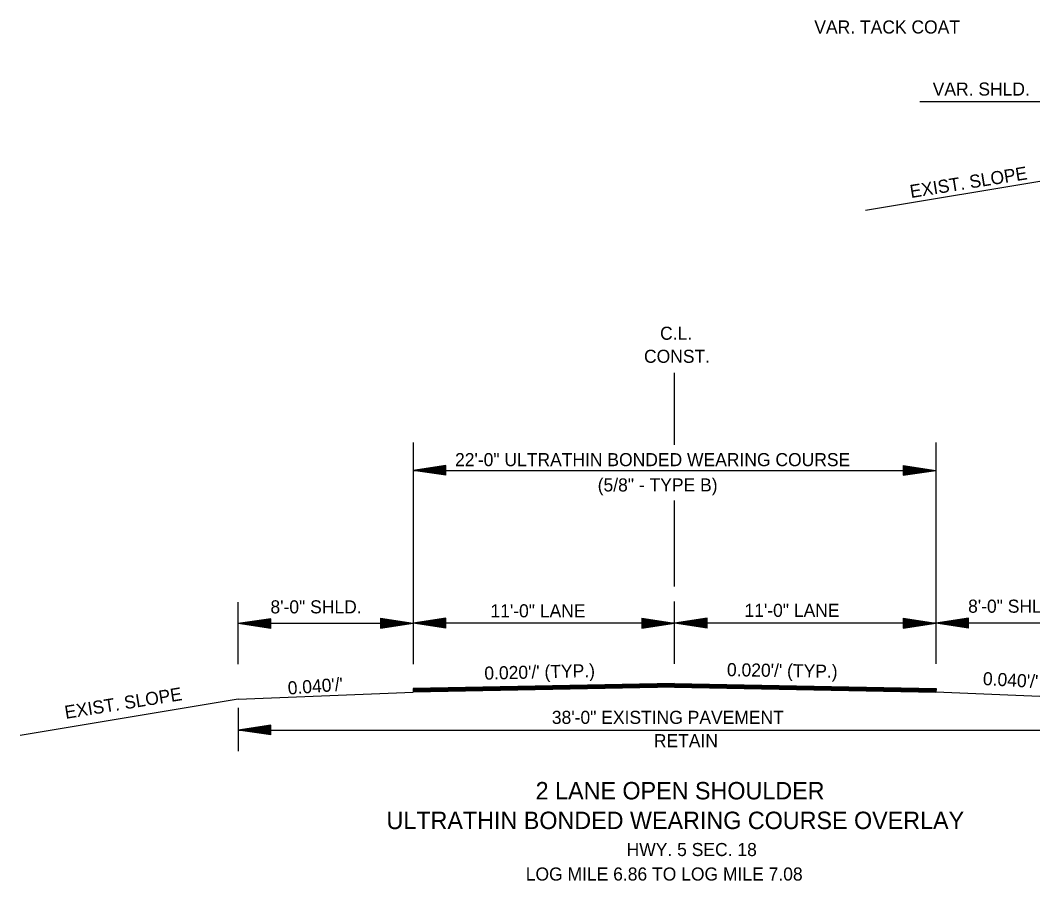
# Model space of a CAD drawing. Extents: x 2263886 to 2266026, y -3122850 to -3121850.
# Drawn here: x 2265375.37 to 2265421.84, y -3122647.18 to -3122607.69 of the extents above; entities that cross this region are included whole.
import ezdxf

# ---------------------------------------------------------------- set-up
doc = ezdxf.new("R2010")
doc.units = 0
doc.layers.add('Default', color=7, linetype='Continuous')
doc.layers.add('R_Border Prem', color=7, linetype='Continuous')

msp = doc.modelspace()

# ---------------------------------------------------------------- linework, layer by layer
at = {"layer": 'R_Border Prem'}
for p, q in [((2265428.196, -3122611.431), (2265416.655, -3122611.431)), ((2265424.167, -3122614.746), (2265414.16, -3122616.414)), ((2265405.399, -3122627.168), (2265405.399, -3122623.874)), ((2265393.399, -3122627.069), (2265393.399, -3122637.242)), ((2265394.899, -3122628.119), (2265393.399, -3122628.344)), ((2265394.899, -3122628.157), (2265393.65, -3122628.344)), ((2265394.899, -3122628.195), (2265393.908, -3122628.344)), ((2265394.899, -3122628.233), (2265394.158, -3122628.344)), ((2265394.899, -3122628.271), (2265394.412, -3122628.344)), ((2265394.899, -3122628.309), (2265394.662, -3122628.344)), ((2265394.899, -3122628.569), (2265394.899, -3122628.119)), ((2265415.892, -3122628.119), (2265417.392, -3122628.344)), ((2265415.892, -3122628.119), (2265415.892, -3122628.569)), ((2265415.892, -3122628.157), (2265417.142, -3122628.344)), ((2265415.892, -3122628.195), (2265416.884, -3122628.344)), ((2265415.892, -3122628.233), (2265416.634, -3122628.344)), ((2265415.892, -3122628.272), (2265416.38, -3122628.344)), ((2265415.892, -3122628.309), (2265416.129, -3122628.344)), ((2265393.399, -3122628.344), (2265417.392, -3122628.344)), ((2265394.899, -3122628.569), (2265393.399, -3122628.344)), ((2265394.899, -3122628.532), (2265393.65, -3122628.344)), ((2265394.899, -3122628.494), (2265393.908, -3122628.344)), ((2265394.899, -3122628.456), (2265394.158, -3122628.344)), ((2265394.899, -3122628.417), (2265394.412, -3122628.344)), ((2265394.899, -3122628.38), (2265394.662, -3122628.344)), ((2265415.892, -3122628.569), (2265417.392, -3122628.344)), ((2265415.892, -3122628.418), (2265416.38, -3122628.344)), ((2265415.892, -3122628.494), (2265416.884, -3122628.344)), ((2265415.892, -3122628.532), (2265417.142, -3122628.344)), ((2265415.892, -3122628.456), (2265416.634, -3122628.344)), ((2265415.892, -3122628.38), (2265416.129, -3122628.344)), ((2265405.399, -3122633.668), (2265405.399, -3122629.733)), ((2265385.373, -3122637.242), (2265385.373, -3122634.387)), ((2265405.399, -3122637.225), (2265405.399, -3122634.37)), ((2265386.873, -3122635.151), (2265385.373, -3122635.376)), ((2265386.873, -3122635.188), (2265385.624, -3122635.376)), ((2265386.873, -3122635.227), (2265385.882, -3122635.376)), ((2265386.873, -3122635.264), (2265386.132, -3122635.376)), ((2265386.873, -3122635.601), (2265386.873, -3122635.151)), ((2265391.899, -3122635.134), (2265393.399, -3122635.359)), ((2265391.899, -3122635.134), (2265391.899, -3122635.584)), ((2265391.899, -3122635.171), (2265393.149, -3122635.359)), ((2265391.899, -3122635.21), (2265392.891, -3122635.359)), ((2265391.899, -3122635.247), (2265392.641, -3122635.359)), ((2265391.899, -3122635.286), (2265392.387, -3122635.359)), ((2265394.899, -3122635.134), (2265393.399, -3122635.359)), ((2265394.899, -3122635.171), (2265393.65, -3122635.359)), ((2265394.899, -3122635.21), (2265393.908, -3122635.359)), ((2265394.899, -3122635.247), (2265394.158, -3122635.359)), ((2265394.899, -3122635.285), (2265394.412, -3122635.359)), ((2265394.899, -3122635.584), (2265394.899, -3122635.134)), ((2265403.899, -3122635.134), (2265405.399, -3122635.359)), ((2265403.899, -3122635.134), (2265403.899, -3122635.584)), ((2265403.899, -3122635.171), (2265405.149, -3122635.359)), ((2265403.899, -3122635.21), (2265404.891, -3122635.359)), ((2265403.899, -3122635.247), (2265404.641, -3122635.359)), ((2265403.899, -3122635.286), (2265404.387, -3122635.359)), ((2265406.899, -3122635.134), (2265405.399, -3122635.359)), ((2265406.899, -3122635.171), (2265405.65, -3122635.359)), ((2265406.899, -3122635.21), (2265405.908, -3122635.359)), ((2265406.899, -3122635.247), (2265406.158, -3122635.359)), ((2265406.899, -3122635.285), (2265406.412, -3122635.359)), ((2265406.899, -3122635.584), (2265406.899, -3122635.134)), ((2265415.892, -3122635.134), (2265417.392, -3122635.359)), ((2265415.892, -3122635.134), (2265415.892, -3122635.584)), ((2265415.892, -3122635.171), (2265417.142, -3122635.359)), ((2265415.892, -3122635.21), (2265416.884, -3122635.359)), ((2265415.892, -3122635.247), (2265416.634, -3122635.359)), ((2265415.892, -3122635.286), (2265416.38, -3122635.359)), ((2265418.892, -3122635.134), (2265417.392, -3122635.359)), ((2265418.892, -3122635.171), (2265417.643, -3122635.359)), ((2265418.892, -3122635.21), (2265417.901, -3122635.359)), ((2265418.892, -3122635.247), (2265418.15, -3122635.359)), ((2265418.892, -3122635.285), (2265418.405, -3122635.359)), ((2265418.892, -3122635.584), (2265418.892, -3122635.134)), ((2265393.399, -3122635.376), (2265385.373, -3122635.376)), ((2265386.873, -3122635.601), (2265385.373, -3122635.376)), ((2265386.873, -3122635.563), (2265385.624, -3122635.376)), ((2265386.873, -3122635.525), (2265385.882, -3122635.376)), ((2265386.873, -3122635.488), (2265386.132, -3122635.376)), ((2265386.873, -3122635.302), (2265386.386, -3122635.376)), ((2265386.873, -3122635.449), (2265386.386, -3122635.376)), ((2265386.873, -3122635.341), (2265386.636, -3122635.376)), ((2265386.873, -3122635.411), (2265386.636, -3122635.376)), ((2265391.899, -3122635.324), (2265392.136, -3122635.359)), ((2265391.899, -3122635.584), (2265393.399, -3122635.359)), ((2265391.899, -3122635.432), (2265392.387, -3122635.359)), ((2265391.899, -3122635.508), (2265392.891, -3122635.359)), ((2265391.899, -3122635.546), (2265393.149, -3122635.359)), ((2265391.899, -3122635.471), (2265392.641, -3122635.359)), ((2265391.899, -3122635.394), (2265392.136, -3122635.359)), ((2265405.399, -3122635.359), (2265393.399, -3122635.359)), ((2265394.899, -3122635.584), (2265393.399, -3122635.359)), ((2265394.899, -3122635.546), (2265393.65, -3122635.359)), ((2265394.899, -3122635.508), (2265393.908, -3122635.359)), ((2265394.899, -3122635.471), (2265394.158, -3122635.359)), ((2265394.899, -3122635.432), (2265394.412, -3122635.359)), ((2265394.899, -3122635.324), (2265394.662, -3122635.359)), ((2265394.899, -3122635.394), (2265394.662, -3122635.359)), ((2265403.899, -3122635.324), (2265404.136, -3122635.359)), ((2265403.899, -3122635.584), (2265405.399, -3122635.359)), ((2265403.899, -3122635.432), (2265404.387, -3122635.359)), ((2265403.899, -3122635.508), (2265404.891, -3122635.359)), ((2265403.899, -3122635.546), (2265405.149, -3122635.359)), ((2265403.899, -3122635.471), (2265404.641, -3122635.359)), ((2265403.899, -3122635.394), (2265404.136, -3122635.359)), ((2265417.392, -3122635.359), (2265405.399, -3122635.359)), ((2265406.899, -3122635.584), (2265405.399, -3122635.359)), ((2265406.899, -3122635.546), (2265405.65, -3122635.359)), ((2265406.899, -3122635.508), (2265405.908, -3122635.359)), ((2265406.899, -3122635.471), (2265406.158, -3122635.359)), ((2265406.899, -3122635.432), (2265406.412, -3122635.359)), ((2265406.899, -3122635.324), (2265406.662, -3122635.359)), ((2265406.899, -3122635.394), (2265406.662, -3122635.359)), ((2265415.892, -3122635.324), (2265416.129, -3122635.359)), ((2265415.892, -3122635.584), (2265417.392, -3122635.359)), ((2265415.892, -3122635.432), (2265416.38, -3122635.359)), ((2265415.892, -3122635.508), (2265416.884, -3122635.359)), ((2265415.892, -3122635.546), (2265417.142, -3122635.359)), ((2265415.892, -3122635.471), (2265416.634, -3122635.359)), ((2265415.892, -3122635.394), (2265416.129, -3122635.359)), ((2265425.418, -3122635.359), (2265417.392, -3122635.359)), ((2265418.892, -3122635.584), (2265417.392, -3122635.359)), ((2265418.892, -3122635.546), (2265417.643, -3122635.359)), ((2265418.892, -3122635.508), (2265417.901, -3122635.359)), ((2265418.892, -3122635.471), (2265418.15, -3122635.359)), ((2265418.892, -3122635.432), (2265418.405, -3122635.359)), ((2265418.892, -3122635.324), (2265418.655, -3122635.359)), ((2265418.892, -3122635.394), (2265418.655, -3122635.359)), ((2265385.373, -3122638.85), (2265393.403, -3122638.529)), ((2265405.399, -3122638.119), (2265393.399, -3122638.359)), ((2265393.399, -3122638.359), (2265393.403, -3122638.529)), ((2265405.4, -3122638.149), (2265393.4, -3122638.389)), ((2265405.401, -3122638.179), (2265393.401, -3122638.419)), ((2265405.401, -3122638.209), (2265393.401, -3122638.449)), ((2265405.402, -3122638.239), (2265393.402, -3122638.479)), ((2265405.402, -3122638.269), (2265393.402, -3122638.509)), ((2265405.403, -3122638.289), (2265393.403, -3122638.529)), ((2265405.396, -3122638.269), (2265417.396, -3122638.509)), ((2265405.396, -3122638.289), (2265417.396, -3122638.529)), ((2265405.397, -3122638.239), (2265417.397, -3122638.479)), ((2265405.398, -3122638.179), (2265417.398, -3122638.419)), ((2265405.398, -3122638.209), (2265417.398, -3122638.449)), ((2265405.399, -3122638.119), (2265417.399, -3122638.359)), ((2265405.399, -3122638.149), (2265417.399, -3122638.389)), ((2265417.399, -3122638.359), (2265417.396, -3122638.529)), ((2265425.425, -3122638.85), (2265417.396, -3122638.529)), ((2265385.373, -3122638.85), (2265375.366, -3122640.518)), ((2265385.373, -3122639.236), (2265385.373, -3122641.236)), ((2265386.873, -3122640.036), (2265385.373, -3122640.261)), ((2265385.373, -3122640.261), (2265425.418, -3122640.261)), ((2265386.873, -3122640.486), (2265385.373, -3122640.261)), ((2265386.873, -3122640.073), (2265385.624, -3122640.261)), ((2265386.873, -3122640.448), (2265385.624, -3122640.261)), ((2265386.873, -3122640.112), (2265385.882, -3122640.261)), ((2265386.873, -3122640.41), (2265385.882, -3122640.261)), ((2265386.873, -3122640.149), (2265386.132, -3122640.261)), ((2265386.873, -3122640.373), (2265386.132, -3122640.261)), ((2265386.873, -3122640.187), (2265386.386, -3122640.261)), ((2265386.873, -3122640.334), (2265386.386, -3122640.261)), ((2265386.873, -3122640.226), (2265386.636, -3122640.261)), ((2265386.873, -3122640.296), (2265386.636, -3122640.261)), ((2265386.873, -3122640.486), (2265386.873, -3122640.036))]:
    msp.add_line(p, q, dxfattribs=at)
msp.add_lwpolyline([(2265417.392, -3122627.069), (2265417.392, -3122637.225)], dxfattribs=at)

# ---------------------------------------------------------------- texts
at = {"layer": 'Default'}
for s, p in [('38\'-0" EXISTING PAVEMENT', (2265399.765, -3122639.979)), ('RETAIN', (2265404.447, -3122641.051))]:
    msp.add_text(s, height=0.6, dxfattribs=at).set_placement(p)
at = {"layer": 'R_Border Prem'}
for s, height, p in [('VAR. TACK COAT', 0.6, (2265411.811, -3122608.298)), ('VAR. SHLD. ', 0.6, (2265417.245, -3122611.146)), ('C.L.', 0.6, (2265404.732, -3122622.353)), ('CONST.', 0.6, (2265403.995, -3122623.41)), ('22\'-0" ULTRATHIN BONDED WEARING COURSE', 0.6, (2265395.322, -3122628.153)), ('(5/8" - TYPE B)', 0.6, (2265401.869, -3122629.313)), ('8\'-0" SHLD.', 0.6, (2265386.85, -3122634.908)), ('8\'-0" SHLD.', 0.6, (2265418.869, -3122634.878)), ('11\'-0" LANE', 0.6, (2265396.947, -3122635.09)), ('11\'-0" LANE', 0.6, (2265408.606, -3122635.068)), ('2 LANE OPEN SHOULDER ', 0.8, (2265399.021, -3122643.445)), ('ULTRATHIN BONDED WEARING COURSE OVERLAY', 0.8, (2265392.177, -3122644.807)), ('HWY. 5 SEC. 18', 0.6, (2265403.197, -3122646.045)), ('LOG MILE 6.86 TO LOG MILE 7.08', 0.6, (2265398.567, -3122647.169))]:
    msp.add_text(s, height=height, dxfattribs=at).set_placement(p)
for s, rotation, p in [('EXIST. SLOPE', 9.1534, (2265416.248, -3122615.85)), ("0.020'/' (TYP.)", 1.4254, (2265396.674, -3122637.954)), ("0.020'/' (TYP.)", 359.0628, (2265407.797, -3122637.787)), ("0.040'/'", 356.7966, (2265419.537, -3122638.195)), ("0.040'/'", 4.2524, (2265387.666, -3122638.637)), ('EXIST. SLOPE', 9.1534, (2265377.454, -3122639.751))]:
    msp.add_text(s, height=0.6, rotation=rotation, dxfattribs=at).set_placement(p)

doc.saveas('drawing.dxf')
